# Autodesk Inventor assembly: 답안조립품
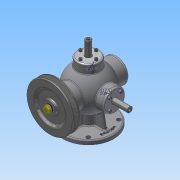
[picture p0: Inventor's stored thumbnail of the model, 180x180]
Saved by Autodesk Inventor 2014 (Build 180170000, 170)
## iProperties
Created: 2016-01
Part Number: 답안조립품
Document SubType Name: Assembly
Designer: Administrator
Author: Administrator
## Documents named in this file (17)
- C:\Users\Administrator\Desktop\360108V1007\답안조립품.iam
- C:\Users\Administrator\Desktop\360108V1007\본체.ipt
- C:\Users\Administrator\Desktop\360108V1007\V-벨트풀리.ipt
- C:\Users\Administrator\Desktop\360108V1007\너트-M8x1.ipt
- C:\Users\Administrator\Desktop\360108V1007\뒤커버.ipt
- C:\Users\Administrator\Desktop\360108V1007\본체커버.ipt
- C:\Users\Administrator\Desktop\360108V1007\앞커버.ipt
- C:\Users\Administrator\Desktop\360108V1007\오일실.ipt
- C:\Users\Administrator\Desktop\360108V1007\와셔 8x17.ipt
- C:\Users\Administrator\Desktop\360108V1007\축.ipt
- C:\Users\Administrator\Desktop\360108V1007\키-4x4.ipt
- C:\Users\Administrator\Desktop\360108V1007\베어링- 6202.ipt
- C:\Users\Administrator\Desktop\360108V1007\슬라이드 커버.ipt
- C:\Users\Administrator\Desktop\360108V1007\슬라이드.ipt
- C:\Users\Administrator\Desktop\360108V1007\볼트 M4x0.7.ipt
- C:\Users\Administrator\Desktop\360108V1007\스프링1.ipt
- C:\Users\Administrator\Desktop\360108V1007\스프링2.ipt
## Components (18 placed, 2 different names)
1. V-벨트풀리:1 — 각도:2
2. M4x0.7x12:3
3. M4x0.7x12:2
4. M4x0.7x12:6
5. M4x0.7x12:7
6. M4x0.7x12:8
7. M4x0.7x12:4
8. M4x0.7x12:9
9. M4x0.7x12:10
10. M4x0.7x12:11
11. M4x0.7x12:5
12. M4x0.7x12:12
13. M4x0.7x12:13
14. M4x0.7x12:14
15. M4x0.7x12:1
16. M4x0.7x12:15
17. M4x0.7x12:16
18. M4x0.7x12:17
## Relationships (1: Angle 1)
- 각도:2 [Angle]: V-벨트풀리:1
